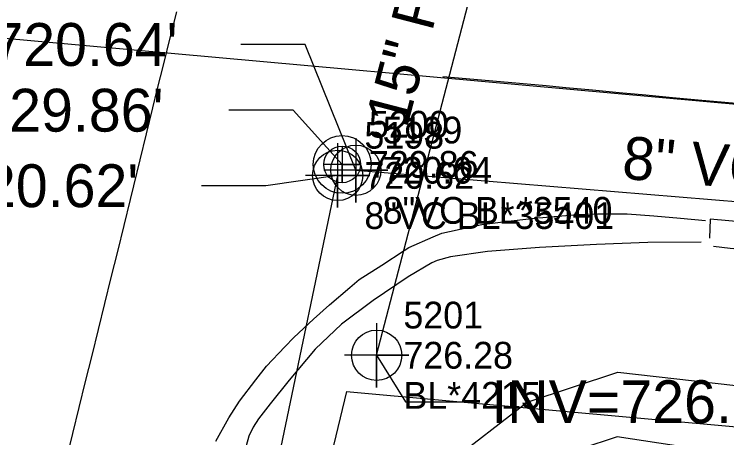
# Model space of a CAD drawing. Extents: x 1516784 to 1522736, y 634838 to 639369.
# Drawn here: x 1520579.8 to 1520646.3, y 638763.1 to 638802.7 of the extents above; entities that cross this region are included whole.
import ezdxf

# ---------------------------------------------------------------- set-up
doc = ezdxf.new("R2010")
doc.units = 0
for name, color, linetype in [('COGO Default Point Elevation', 7, 'Continuous'), ('COGO Default Point Number', 7, 'Continuous'), ('Exist Environmental Wetland Boundary Cogo Number', 7, 'Continuous'), ('Exist Environmental Wetland Boundary Text', 7, 'Continuous'), ('Exist Right of Way Line', 7, 'Continuous'), ('Exist Structure Minor Pipes RCP 15 Inch', 7, 'Continuous'), ('Exist Structure Minor Pipes RCP 15 Inch Cogo Comment', 7, 'Continuous'), ('Exist Structure Minor Pipes RCP 15 Inch Cogo Elevation', 7, 'Continuous'), ('Exist Structure Minor Pipes RCP 15 Inch Cogo Number', 7, 'Continuous'), ('Exist Structure Minor Pipes RCP 15 Inch Cogo Point CELL', 7, 'Continuous'), ('Exist Structure Minor Pipes RCP 15 Inch Invert', 7, 'Continuous'), ('Exist Structure Minor Pipes RCP 15 Inch Leader', 7, 'Continuous'), ('Exist Structure Minor Pipes RCP 15 Inch Text', 7, 'Continuous'), ('Exist Utilities Sanitary Sewer Manhole CELL', 7, 'Continuous'), ('Exist Utilities Sanitary Sewer Manhole Cogo Elevation', 7, 'Continuous'), ('Exist Utilities Sanitary Sewer Manhole Cogo Number', 7, 'Continuous'), ('Exist Utilities Sanitary Sewer Manhole Leader', 7, 'Continuous'), ('Exist Utilities Sanitary Sewer Manhole Text', 7, 'Continuous'), ('Exist Utilities Sanitary Sewer UG Line', 7, 'Continuous'), ('Exist Utilities Sanitary Sewer UG Line Cogo Comment', 7, 'Continuous'), ('Exist Utilities Sanitary Sewer UG Line Cogo Elevation', 7, 'Continuous'), ('Exist Utilities Sanitary Sewer UG Line Cogo Number', 7, 'Continuous'), ('Exist Utilities Sanitary Sewer UG Line Cogo Point CELL', 7, 'Continuous'), ('Exist Utilities Sanitary Sewer UG Line Invert Elevation', 7, 'Continuous'), ('Exist Utilities Sanitary Sewer UG Line Leader', 7, 'Continuous'), ('Exist Utilities Sanitary Sewer UG Line Text', 7, 'Continuous'), ('Exist Vegetation Hedge Row', 7, 'Continuous')]:
    doc.layers.add(name, color=color, linetype=linetype)

msp = doc.modelspace()

# ---------------------------------------------------------------- linework, layer by layer
at = {"layer": 'COGO Default Point Elevation'}
for points in [[(1520584.631, 638761.116), (1520585.23, 638763.543), (1520585.829, 638765.97), (1520586.428, 638768.397), (1520587.027, 638770.823), (1520587.627, 638773.25), (1520588.226, 638775.677), (1520588.825, 638778.103), (1520589.424, 638780.53), (1520590.023, 638782.957), (1520590.623, 638785.383), (1520590.938, 638786.662), (1520591.527, 638789.091), (1520592.116, 638791.52), (1520592.704, 638793.95), (1520593.113, 638795.638), (1520593.723, 638798.062), (1520594.332, 638800.487), (1520594.941, 638802.911)], [(1520648.569, 638794.224), (1520646.08, 638794.45), (1520643.59, 638794.676), (1520641.204, 638794.893), (1520638.716, 638795.125), (1520636.227, 638795.357), (1520633.738, 638795.589), (1520631.25, 638795.821), (1520629.415, 638795.992), (1520626.926, 638796.215), (1520624.437, 638796.438), (1520621.947, 638796.661), (1520619.773, 638796.855)], [(1520598.57, 638762.822), (1520599.797, 638765.019), (1520600.791, 638766.573), (1520602.325, 638768.547), (1520603.318, 638769.824), (1520605.037, 638771.637), (1520605.868, 638772.513), (1520607.707, 638774.205), (1520609.184, 638775.563), (1520611.094, 638777.176), (1520611.968, 638777.914), (1520614.069, 638779.268), (1520616.17, 638780.622), (1520616.596, 638780.896), (1520618.879, 638781.912), (1520619.667, 638782.262), (1520622.112, 638782.781), (1520623.405, 638783.055), (1520625.885, 638783.369), (1520626.13, 638783.4), (1520628.615, 638783.672), (1520629.099, 638783.725), (1520631.591, 638783.926), (1520632.307, 638783.984), (1520634.265, 638784.054), (1520636.764, 638784.052), (1520636.958, 638784.052), (1520639.464, 638783.854), (1520641.955, 638783.635), (1520644.276, 638783.431)]]:
    msp.add_lwpolyline(points, dxfattribs=at)
at = {"layer": 'COGO Default Point Number'}
for points in [[(1520759.384, 638773.113), (1520751.227, 638773.872), (1520742.357, 638774.706), (1520733.424, 638775.545), (1520725.082, 638776.318), (1520717.075, 638777.048), (1520709.145, 638777.756), (1520701.9, 638778.403), (1520695.944, 638778.948), (1520686.785, 638779.78), (1520678.131, 638780.56), (1520668.809, 638781.393), (1520659.466, 638782.228), (1520649.95, 638783.093), (1520644.722, 638783.557), (1520644.664, 638781.797)], [(1520643.865, 638781.394), (1520638.914, 638781.38), (1520634.124, 638781.193), (1520628.78, 638780.925), (1520623.951, 638780.546), (1520620.481, 638780.036), (1520619.246, 638779.7), (1520618.728, 638779.493), (1520616.537, 638778.173), (1520613.263, 638775.965), (1520610.323, 638773.749), (1520607.867, 638771.422), (1520605.418, 638768.513), (1520603.664, 638766.314), (1520602.554, 638764.9), (1520602.057, 638764.127), (1520601.669, 638763.297), (1520601.076, 638761.155)]]:
    msp.add_lwpolyline(points, dxfattribs=at)
at = {"layer": 'Exist Environmental Wetland Boundary Cogo Number'}
msp.add_lwpolyline([(1520758.64, 638770.592), (1520751.694, 638771.23), (1520744.543, 638771.89), (1520736.935, 638772.588), (1520729.202, 638773.288), (1520721.677, 638773.956), (1520714.318, 638774.61), (1520707.084, 638775.27), (1520700.067, 638775.926), (1520693.359, 638776.567), (1520686.657, 638777.208), (1520679.659, 638777.864), (1520671.928, 638778.571), (1520663.026, 638779.364), (1520655.354, 638780.039), (1520651.309, 638780.391), (1520649.358, 638780.561), (1520647.967, 638780.689), (1520646.595, 638780.83), (1520645.033, 638781.003)], dxfattribs=at)
at = {"layer": 'Exist Environmental Wetland Boundary Text'}
msp.add_line((1520569.383, 638801.322), (1520948.554, 638767.08), dxfattribs=at)
msp.add_arc((1524257.184, 637884.739), 3800, 164.443563, 171.459425, dxfattribs=at)
at = {"layer": 'Exist Right of Way Line'}
msp.add_line((1520610.767, 638767.463), (1521229.82, 638711.557), dxfattribs=at)
msp.add_arc((1524257.184, 637884.739), 3751.74, 166.391655, 170.561715, dxfattribs=at)
at = {"layer": 'Exist Structure Minor Pipes RCP 15 Inch'}
msp.add_line((1520613.587, 638770.851), (1520627.821, 638825.568), dxfattribs=at)
at = {"layer": 'Exist Structure Minor Pipes RCP 15 Inch Cogo Point CELL'}
msp.add_lwpolyline([(1520613.587, 638773.851), (1520613.587, 638767.851), (1520613.587, 638770.851), (1520616.587, 638770.851), (1520610.587, 638770.851)], dxfattribs=at)
msp.add_circle((1520613.587, 638770.851), 2.344, dxfattribs=at)
at = {"layer": 'Exist Structure Minor Pipes RCP 15 Inch Leader'}
msp.add_lwpolyline([(1520613.587, 638770.851), (1520616.292, 638766.513), (1520622.292, 638766.513)], dxfattribs=at)
at = {"layer": 'Exist Utilities Sanitary Sewer Manhole CELL'}
msp.add_lwpolyline([(1520610.37, 638790.38), (1520610.37, 638786.955), (1520610.37, 638788.668), (1520612.083, 638788.668), (1520608.657, 638788.668)], dxfattribs=at)
for radius in [2.694, 1.712]:
    msp.add_circle((1520610.37, 638788.668), radius, dxfattribs=at)
at = {"layer": 'Exist Utilities Sanitary Sewer Manhole Leader'}
msp.add_lwpolyline([(1520610.37, 638788.668), (1520605.792, 638793.73), (1520599.792, 638793.73)], dxfattribs=at)
at = {"layer": 'Exist Utilities Sanitary Sewer UG Line'}
for p, q in [((1520611.649, 638788.125), (1520762.779, 638775.704)), ((1520609.949, 638787.641), (1520559.217, 638545.868))]:
    msp.add_line(p, q, dxfattribs=at)
at = {"layer": 'Exist Utilities Sanitary Sewer UG Line Cogo Point CELL'}
for points in [[(1520611.649, 638791.125), (1520611.649, 638785.125), (1520611.649, 638788.125), (1520614.649, 638788.125), (1520608.649, 638788.125)], [(1520609.949, 638790.641), (1520609.949, 638784.641), (1520609.949, 638787.641), (1520612.949, 638787.641), (1520606.949, 638787.641)]]:
    msp.add_lwpolyline(points, dxfattribs=at)
for centre in [(1520611.649, 638788.125), (1520609.949, 638787.641)]:
    msp.add_circle(centre, 2.344, dxfattribs=at)
at = {"layer": 'Exist Utilities Sanitary Sewer UG Line Leader'}
for points in [[(1520611.649, 638788.125), (1520606.912, 638799.864), (1520600.912, 638799.864)], [(1520609.949, 638787.641), (1520603.249, 638786.679), (1520597.249, 638786.679)]]:
    msp.add_lwpolyline(points, dxfattribs=at)
at = {"layer": 'Exist Vegetation Hedge Row'}
msp.add_lwpolyline([(1520745.759, 638749.534), (1520669.416, 638758.177), (1520636.026, 638763.233), (1520629.243, 638760.998), (1520626.017, 638754.164), (1520621.513, 638729.45), (1520612.723, 638730.807), (1520616.88, 638753.78), (1520620.08, 638760.629), (1520627.631, 638766.479), (1520636.09, 638769.277), (1520677.648, 638764.587), (1520752.585, 638757.221)], dxfattribs=at)

# ---------------------------------------------------------------- texts
at = {"layer": 'Exist Structure Minor Pipes RCP 15 Inch Cogo Comment'}
msp.add_text('BL*4215', height=2.5, dxfattribs=at).set_placement((1520616.087, 638765.851))
at = {"layer": 'Exist Structure Minor Pipes RCP 15 Inch Cogo Elevation'}
msp.add_text('726.28', height=2.5, dxfattribs=at).set_placement((1520616.087, 638769.601))
at = {"layer": 'Exist Structure Minor Pipes RCP 15 Inch Cogo Number'}
msp.add_text('5201', height=2.5, dxfattribs=at).set_placement((1520616.087, 638773.351))
at = {"layer": 'Exist Structure Minor Pipes RCP 15 Inch Invert'}
msp.add_text("INV=726.28'", height=4, dxfattribs=at).set_placement((1520624.292, 638764.513))
at = {"layer": 'Exist Structure Minor Pipes RCP 15 Inch Text'}
msp.add_text('15" RCP', height=4, rotation=75.41835, dxfattribs=at).set_placement((1520616.406, 638791.956))
at = {"layer": 'Exist Utilities Sanitary Sewer Manhole Cogo Elevation'}
msp.add_text('729.86', height=2.5, dxfattribs=at).set_placement((1520612.87, 638787.418))
at = {"layer": 'Exist Utilities Sanitary Sewer Manhole Cogo Number'}
msp.add_text('5200', height=2.5, dxfattribs=at).set_placement((1520612.87, 638791.168))
at = {"layer": 'Exist Utilities Sanitary Sewer Manhole Text'}
msp.add_text("TOP=729.86'", height=4, dxfattribs=at).set_placement((1520562.201, 638791.73))
at = {"layer": 'Exist Utilities Sanitary Sewer UG Line Cogo Comment'}
for s, p in [('8"VC BL*3540', (1520614.149, 638783.125)), ('8"VC BL*35401', (1520612.449, 638782.641))]:
    msp.add_text(s, height=2.5, dxfattribs=at).set_placement(p)
at = {"layer": 'Exist Utilities Sanitary Sewer UG Line Cogo Elevation'}
for s, p in [('720.64', (1520614.149, 638786.875)), ('720.62', (1520612.449, 638786.391))]:
    msp.add_text(s, height=2.5, dxfattribs=at).set_placement(p)
at = {"layer": 'Exist Utilities Sanitary Sewer UG Line Cogo Number'}
for s, p in [('5199', (1520614.149, 638790.625)), ('5198', (1520612.449, 638790.141))]:
    msp.add_text(s, height=2.5, dxfattribs=at).set_placement(p)
at = {"layer": 'Exist Utilities Sanitary Sewer UG Line Invert Elevation'}
for s, p in [("INV=720.64'", (1520565.59, 638797.864)), ("INV=720.62'", (1520561.926, 638784.679))]:
    msp.add_text(s, height=4, dxfattribs=at).set_placement(p)
at = {"layer": 'Exist Utilities Sanitary Sewer UG Line Text'}
msp.add_text('8" VC', height=4, rotation=355.30156, dxfattribs=at).set_placement((1520636.419, 638787.343))

doc.saveas('drawing.dxf')
